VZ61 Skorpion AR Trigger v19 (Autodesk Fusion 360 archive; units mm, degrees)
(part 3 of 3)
sketch "Sketch4" plane through (0, 5.5844, 0) normal (0, -1, 0) x axis (1, 0, 0)
  line L1 (6.8359, 50.875) -> (6.8359, 44)
  line L2 (5.4872, 50.875) -> (6.8359, 50.875)
  line L3 (-6.8359, 50.875) -> (-5.4872, 50.875)
  line L4 (-6.8359, 44) -> (-6.8359, 50.875)
  line L5 (6.8359, 44) -> (-6.8359, 44)
  line L6 (6.8359, 50.5) -> (-6.8359, 50.5)
  line L7 (6.8359, 52) -> (-6.8359, 52)
  line L8 (-6.8359, 50.5) -> (-6.8359, 52)
  line L9 (6.8359, 52) -> (6.8359, 50.5)
  line L10 (-0.5, 51.5) -> (-4.4371, 52)
  line L11 (-0.5, 51) -> (-0.5, 51.5)
  line L12 (-4.4371, 50.5) -> (-0.5, 51)
  line L13 (4.4371, 52) -> (0.5, 51.5)
  line L14 (0.5, 51) -> (0.5, 51.5)
  line L15 (4.4371, 50.5) -> (0.5, 51)
  circle C1 centre (0, 51.25) radius 4.5
  arc A1 centre (0, 51.25) radius 5.5 clockwise from (-5.4872, 50.875) to (5.4872, 50.875)
  circle C2 centre (0, 51.25) radius 4.5
  circle C3 centre (0, 51.25) radius 5.5
  circle C4 centre (0, 51.25) radius 6.8359
  point P11 (-6.8359, 50.5)
  point P12 (6.8359, 50.5)
  point P15 (6.8359, 52)
  point P14 (6.8359, 52)
  point P17 (-4.4371, 52)
  point P20 (-4.4371, 50.5)
  point P22 (4.4371, 52)
  point P24 (4.4371, 50.5)
  point P10 (0, 51.25)
  point P21 (0.5, 51.5)
  point P23 (0.5, 51)
  concentric C1 C2
  concentric C1 C3
  coincident L4 P11
  coincident L1 P12
  perpendicular L1 L6
  horizontal L7
  perpendicular L6 L8
  coincident L7 P15
  perpendicular L7 L9
  coincident P14 P15
  concentric C2 C4
  coincident C2 P17
  coincident L7 P17
  perpendicular L6 L11
  coincident L6 P20
  coincident C2 P20
  coincident C2 P22
  coincident L7 P22
  perpendicular L7 L14
  coincident C2 P24
  coincident L6 P24
  dimension "d16" distance P10 L6 = 0.75 (= "( 1.5 / 2 ) * 1 mm")
  dimension "d17" distance P10 L7 = 0.75
  dimension "d38" distance P21 P23 = 0.5
extrude "Extrude5" cut sketch "Sketch4" profile of C1 L1 L2 A1 L3 L4 C2 C3 L6 L7 L8 L9 against normal blind 2
extrude "Extrude6" cut sketch "Sketch4" profile of L1 L2 C3 L6 L9 against normal blind 2
extrude "Extrude7" cut sketch "Sketch4" profile of C1 A1 C2 C3 L7 against normal blind 2
extrude "Extrude8" cut sketch "Sketch4" profile of C1 C2 C3 L6 against normal blind 2
extrude "Extrude9" cut sketch "Sketch4" profile of C1 A1 C2 C3 L6 L7 against normal blind 2
extrude "Extrude10" cut sketch "Sketch4" profile of C1 A1 C2 C3 L6 L7 against normal blind 2
extrude "Extrude11" new body sketch "Sketch4" profile of C1 A1 C2 C3 L6 L7 against normal blind 2
extrude "Extrude12" new body sketch "Sketch4" profile of L1 L2 A1 L3 L4 C3 L6 L7 L8 L9 against normal blind 2
extrude "Extrude13" new body of existing geometry blind 1.125
extrude "Extrude14" new body sketch "Sketch4" profile of A1 C3 L7 C4 against normal blind 15
combine "Combine1"
combine "Combine2"
combine "Combine3"
delete_face "DeleteFace1"
delete_face "DeleteFace2"
extrude "Extrude15" new body sketch "Sketch4" profile of C1 C2 L8 L10 L11 L12 L13 L14 L15 against normal blind 2 bodies "Rear Sight Ring"
combine "Combine4"
sketch "Sketch5" plane through (10.6045, 0, 0) normal (1, 0, 0) x axis (0, 1, 0)
  line L1 (34.9974, 44) -> (5.5844, 44)
  line L2 (34.9974, 57) -> (34.9974, 44)
  line L3 (5.5844, 57) -> (34.9974, 57)
  line L4 (5.5844, 44) -> (5.5844, 57)
  line L5 (5.5844, 44.4141) -> (5.5844, 58.0859)
  circle C1 centre (14.5844, 46.5) radius 2
  circle C2 centre (14.5844, 46.5) radius 1
  point P7 (14.5844, 46.5)
  point P6 (14.5844, 46.5)
  concentric C1 C2
  dimension "d41" diameter C1 = 4
  dimension "d42" diameter C2 = 2
  dimension "d73" distance L1 P7 = 2.5
  dimension "d74" distance P6 L5 = 9
sketch "Sketch6" plane through (6.8359, 0, 0) normal (1, 0, 0) x axis (0, 1, 0)
  line L1 (20.5844, 52) -> (20.5844, 44)
  line L2 (7.5844, 52) -> (20.5844, 52)
  line L3 (7.5844, 50.5) -> (7.5844, 52)
  line L4 (5.5844, 50.5) -> (7.5844, 50.5)
  line L5 (5.5844, 44) -> (5.5844, 50.5)
  line L6 (20.5844, 44) -> (5.5844, 44)
  line L7 (35, 46.5) -> (35, 44)
  line L8 (20.5844, 46.5) -> (35, 46.5)
  line L9 (35, 46.5) -> (20.5844, 52)
  line L10 (20.5844, 44) -> (35, 44)
  point P10 (20.5844, 46.5)
  point P3 (20.5844, 52)
  point P11 (20.5844, 52)
  point P2 (20.5844, 44)
  point P12 (20.5844, 44)
  perpendicular L2 L7
  coincident L1 P10
  perpendicular L1 L8
  coincident P3 P11
  coincident P2 P12
extrude "Extrude16" new body sketch "Sketch6" profile of L1 L7 L8 L9 L10 against normal blind 13.672 bodies "Rear Sight Fixture"
sketch "Sketch7" plane through (0, 20.5844, 0) normal (0, 1, 0) x axis (-1, 0, 0)
  line L1 (6.8359, 52) -> (6.8359, 44)
  line L2 (6.7946, 52) -> (6.8359, 52)
  line L3 (-6.8359, 52) -> (-6.7946, 52)
  line L4 (-6.8359, 44) -> (-6.8359, 52)
  line L5 (6.8359, 44) -> (-6.8359, 44)
  arc A1 centre (0, 51.25) radius 6.8359 clockwise from (-6.7946, 52) to (6.7946, 52)
  circle C1 centre (0, 51.25) radius 4.5
extrude "Extrude17" cut sketch "Sketch7" profile of C1 along normal blind 25.5
fillet "Fillet1" radius 2.5
sketch "Sketch8" plane through (0, 0, 40.8178) normal (0, 0, -1) x axis (1, 0, 0)
  line L1 (-7.8359, -5.5844) -> (7.8359, -5.5844)
  line L2 (-7.8359, -34.9974) -> (-7.8359, -5.5844)
  line L3 (7.8359, -34.9974) -> (-7.8359, -34.9974)
  line L4 (7.8359, -5.5844) -> (7.8359, -34.9974)
  circle C1 centre (0, -32.2474) radius 1.05
  circle C2 centre (0, -32.2474) radius 2.5
  circle C3 centre (0, -32.2474) radius 2.15
  point P6 (0, -32.2474)
  concentric C1 C2
  concentric C1 C3
  dimension "d48" diameter C1 = 2.1
  dimension "d49" diameter C2 = 5
  dimension "d54" distance L3 P6 = 2.75
  dimension "d55" diameter C3 = 4.3
extrude "Extrude18" cut sketch "Sketch8" profile of L3 C1 C2 against normal blind 1.7
extrude "Extrude19" cut of existing geometry blind -17
extrude "Extrude20" cut sketch "Sketch8" profile of C1 C3 blind 0.1 second side blind 2.5 from offset -6
sketch "Sketch10" plane through (0, 0, 44) normal (0, 0, -1) x axis (1, 0, 0)
  line L1 (-6.8359, -5.5844) -> (6.8359, -5.5844)
  line L2 (-6.8359, -20.5844) -> (-6.8359, -5.5844)
  line L3 (6.8359, -20.5844) -> (-6.8359, -20.5844)
  line L4 (6.8359, -5.5844) -> (6.8359, -20.5844)
  line L5 (12.5, -5.5844) -> (-12.5, -5.5844)
  circle C1 centre (0, -10.0844) radius 1.875
  point P6 (0, -10.0844)
  dimension "d61" diameter C1 = 3.75
  dimension "d62" distance P6 L5 = 4.5
extrude "Extrude21" cut sketch "Sketch10" profile of C1 against normal blind 17.5
sketch "Sketch11" plane through (6.8359, 0, 0) normal (1, 0, 0) x axis (0, 1, 0)
  line L1 (20.5844, 52) -> (35, 46.5)
  line L2 (20.5844, 44) -> (20.5844, 52)
  line L3 (32.5, 44) -> (20.5844, 44)
  line L4 (31.2, 44) -> (31.2, 46.7)
  line L5 (34.9568, 46.0375) -> (33.3, 46.7)
  line L6 (33.3, 46.7) -> (31.2, 46.7)
  line L7 (30.1, 46) -> (32.25, 46.7)
  line L8 (30.1, 46.7) -> (30.1, 46)
  line L9 (32.25, 46.7) -> (30.1, 46.7)
  arc A1 centre (32.5, 46.5) radius 2.5 clockwise from (35, 46.5) to (32.5, 44)
  point P8 (31.2, 44)
  point P10 (34.9568, 46.0375)
  point P11 (32.25, 46.7)
  coincident L3 P8
  perpendicular L3 L4
  coincident A1 P10
  horizontal L6
  midpoint L6 P11
  perpendicular L6 L8
  parallel L6 L9
extrude "Extrude22" cut sketch "Sketch11" profile of A1 L3 L4 L5 L6 L7 L8 L9 blind -2.05 from offset -5.8
extrude "Extrude23" add of existing geometry blind 2.7
delete_face "DeleteFace3"
sketch "Sketch12" plane through (0, 0, 46.7178) normal (0, 0, 1) x axis (-1, 0, 0)
  line L1 (-2.15, -32.2474) -> (0, -32.2474)
  line L2 (2.15, -32.2474) -> (0, -32.2474)
  circle C1 centre (0, -32.2474) radius 1.05
  circle C2 centre (0, -32.2474) radius 2.15
  point P2 (0, -32.2474)
  point P3 (0, -32.2474)
  point P4 (-2.15, -32.2474)
  point P5 (2.15, -32.2474)
  coincident P2 P3
  coincident C2 P4
  horizontal L1
  coincident C2 P5
  parallel L1 L2
revolve "Revolve1" sketch "Sketch12" AlongAngle -10
extrude "Extrude25" cut sketch "Sketch5" profile of C2 against normal blind 26
combine "Combine5"
sketch "Sketch13" plane through (-10.6045, 0, 0) normal (-1, 0, 0) x axis (0, -1, 0)
  line L1 (-5.5844, 44) -> (-34.9974, 44)
  line L2 (-5.5844, 57) -> (-5.5844, 44)
  line L3 (-34.9974, 57) -> (-5.5844, 57)
  line L4 (-34.9974, 44) -> (-34.9974, 57)
  circle C1 centre (-14.5844, 46.5) radius 1
  circle C2 centre (-14.5844, 46.5) radius 2.5
  concentric C1 C2
  dimension "d77" diameter C2 = 5
extrude "Extrude26" cut sketch "Sketch13" profile of C1 C2 against normal blind 2
extrude "Extrude27" cut sketch "Sketch5" profile of C1 C2 against normal blind 2
extrude "Extrude28" cut of existing geometry blind -7
extrude "Extrude29" add of existing geometry blind 3
chamfer "Chamfer1" distance 22 rotateAngle 20
extrude "Extrude31" new body sketch "Base" profile of L1 L7 L8 L9 L11 L12 L13 L14 along normal blind 5 bodies "Front Sight Base"
extrude "Extrude32" new body sketch "Base" profile of L2 L3 L4 L5 L9 L10 L13 L14 along normal blind 5
move "Move1"
combine "Combine6"
extrude "Extrude33" new body of existing geometry blind 3
extrude "Extrude34" new body of existing geometry blind 4.664
combine "Combine7"
combine "Combine8"
sketch "Sketch14" plane through (0, 0.5844, 0) normal (0, -1, 0) x axis (1, 0, 0)
  line L1 (12.5, 31.496) -> (7.8359, 31.496)
  line L2 (12.5, 44) -> (12.5, 31.496)
  line L3 (7.8359, 44) -> (12.5, 44)
  line L4 (7.8359, 40.8178) -> (7.8359, 44)
  line L5 (10.6045, 37.8979) -> (7.8359, 40.8178)
  line L6 (7.8359, 34.9861) -> (10.6045, 37.8979)
  line L7 (7.8359, 31.496) -> (7.8359, 34.9861)
  line L8 (7.8359, 47) -> (7.8359, 44)
  line L9 (10.5, 47) -> (7.8359, 47)
  line L10 (12.5, 47) -> (10.5, 47)
  line L11 (12.5, 44) -> (12.5, 47)
  line L12 (7.8359, 42.8178) -> (5.8359, 42.8178)
  line L13 (7.8359, 40.8178) -> (-7.8359, 40.8178)
  line L14 (5.8359, 44.8178) -> (5.8359, 42.8178)
  line L15 (7.8359, 44.8178) -> (5.8359, 44.8178)
  line L16 (12.5, 44.8178) -> (7.8359, 44.8178)
  point P5 (7.8359, 44)
  point P9 (7.8359, 44)
  point P4 (12.5, 44)
  point P13 (12.5, 44)
  point P15 (7.8359, 42.8178)
  point P19 (7.8359, 44.8178)
  point P20 (12.5, 44.8178)
  point P14 (5.8359, 42.8178)
  point P18 (5.8359, 44.8178)
  coincident P5 P9
  perpendicular L3 L8
  perpendicular L8 L9
  perpendicular L8 L10
  coincident P4 P13
  coincident L4 P15
  perpendicular L4 L12
  perpendicular L12 L14
  coincident L8 P19
  perpendicular L8 L15
  coincident L11 P20
  perpendicular L11 L16
  dimension "d98" distance L12 L13 = 2
  dimension "d99" distance P14 P15 = 2
  dimension "d100" distance P14 P18 = 2
extrude "Extrude35" cut sketch "Sketch14" profile of L3 L8 L9 L10 L11 against normal blind 43
extrude "Extrude36" new body of existing geometry blind 4.664
combine "Combine9"
extrude "Extrude37" cut sketch "Sketch14" profile of L1 L2 L3 L4 L5 L6 L7 L8 L11 L12 L14 L15 L16 against normal blind 59
extrude "Extrude38" new body sketch "Sketch14" profile of L1 L2 L3 L4 L5 L6 L7 L8 L11 L12 L14 L15 L16 against normal blind 34.413 bodies "Rear Sight Clamp"
move "Move2"
sketch "Sketch15" plane through (12.5, 0, 0) normal (1, 0, 0) x axis (0, 1, 0)
  line L1 (0.5844, 31.496) -> (0.5844, 44)
  line L2 (34.9974, 31.496) -> (0.5844, 31.496)
  line L3 (34.9974, 44) -> (34.9974, 31.496)
  line L4 (0.5844, 44) -> (34.9974, 44)
  line L5 (34.9974, 37.8979) -> (0.5844, 37.8979)
  line L6 (19.23, 39.9979) -> (13.9976, 39.9979)
  line L7 (19.23, 37.8979) -> (19.23, 40.8178)
  line L8 (13.9976, 40.8178) -> (13.9976, 37.8979)
  circle C1 centre (16.6138, 39.9979) radius 2.1
  circle C2 centre (16.6138, 39.9979) radius 3.5
  point P10 (19.23, 39.9979)
  point P9 (13.9976, 39.9979)
  point P6 (16.6138, 39.9979)
  tangent C1 L5
  horizontal L6
  coincident P10 L7
  coincident P9 L8
  midpoint P6 L6
  concentric C1 C2
  dimension "d109" diameter C1 = 4.2
  dimension "d110" diameter C2 = 7
extrude "Extrude39" cut sketch "Sketch15" profile of C1 L6 against normal blind 75
extrude "Extrude40" cut sketch "Sketch15" profile of C1 L5 L6 L7 L8 C2 against normal blind 1
sketch "Sketch16" plane through (-12.5, 0, 0) normal (-1, 0, 0) x axis (0, -1, 0)
  line L1 (-0.5844, 31.496) -> (-34.9974, 31.496)
  line L2 (-0.5844, 47) -> (-0.5844, 31.496)
  line L3 (-34.9974, 47) -> (-0.5844, 47)
  line L4 (-34.9974, 31.496) -> (-34.9974, 47)
  circle C1 centre (-16.6138, 39.9979) radius 2.1
  circle C2 centre (-16.6138, 39.9979) radius 4
  concentric C1 C2
  dimension "d115" diameter C2 = 8
extrude "Extrude41" cut sketch "Sketch16" profile of C1 C2 against normal blind 1.75
fillet "Fillet2" radius 2
fillet "Fillet3" radius 2
fillet "Fillet4" radius 2
combine "Combine10"
sketch "Sketch17" plane through (0, 150.04, 0) normal (0, 1, 0) x axis (-1, 0, 0)
  line L1 (-10.6045, 37.8979) -> (-7.8359, 40.8178)
  line L2 (-7.8359, 34.9861) -> (-10.6045, 37.8979)
  line L3 (-7.8359, 31.496) -> (-7.8359, 34.9861)
  line L4 (7.8359, 31.496) -> (-7.8359, 31.496)
  line L5 (7.8359, 35.0314) -> (7.8359, 31.496)
  line L6 (10.6045, 37.9286) -> (7.8359, 35.0314)
  line L7 (7.8359, 40.8178) -> (10.6045, 37.9286)
  line L8 (-7.8359, 40.8178) -> (7.8359, 40.8178)
  line L9 (0.5, 47) -> (0.5, 54.3)
  line L10 (-0.4943, 47) -> (-0.5, 54.2996)
  line L11 (0.5, 47) -> (-0.4943, 47)
  line L12 (-10.4999, 47) -> (10.5, 47)
  line L13 (0.0028, 47) -> (0, 54.3)
  line L14 (-0.0002, 54.8) -> (0, 54.3)
  circle C1 centre (0, 54.3) radius 0.5
  point P11 (0.5, 54.3)
  point P13 (-0.5, 54.2996)
  point P10 (0, 54.3)
  point P17 (0, 54.3)
  point P18 (0.0028, 47)
  point P19 (0, 54.3)
  point P20 (-0.0002, 54.8)
  coincident C1 P11
  tangent C1 L9
  vertical L9
  coincident C1 P13
  tangent C1 L10
  collinear L11 L12
  coincident P10 P17
  midpoint L11 P18
  coincident P10 P19
  coincident C1 P20
  parallel L13 L14
revolve "Revolve2" sketch "Sketch17" AlongAngle 360
copy_paste_bodies "CopyPasteBodies1"
move "Move3"
move_face "MoveFace1"
extrude "Extrude42" cut of existing geometry blind -7
delete_face "DeleteFace4"
sketch "Sketch18" plane through (0, 149.9974, 0) normal (0, 1, 0) x axis (-1, 0, 0)
  line L1 (7.8359, 53.5922) -> (10.6045, 53.5922)
  line L2 (7.8359, 47) -> (7.8359, 53.5922)
  line L3 (-7.8359, 47) -> (7.8359, 47)
  line L4 (-7.8359, 53.5922) -> (-7.8359, 47)
  line L5 (-10.6045, 53.5922) -> (-7.8359, 53.5922)
  line L6 (-10.6045, 47) -> (-10.6045, 53.5922)
  line L7 (-10.4999, 47) -> (-10.6045, 47)
  line L8 (-12.4999, 44.8178) -> (-12.4999, 45)
  line L9 (-7.8359, 44.8178) -> (-12.4999, 44.8178)
  line L10 (-5.8359, 44.8178) -> (-7.8359, 44.8178)
  line L11 (-5.8359, 42.8178) -> (-5.8359, 44.8178)
  line L12 (-7.8359, 42.8178) -> (-5.8359, 42.8178)
  line L13 (-7.8359, 40.8178) -> (-7.8359, 42.8178)
  line L14 (7.8359, 40.8178) -> (-7.8359, 40.8178)
  line L15 (10.6045, 37.9286) -> (7.8359, 40.8178)
  line L16 (7.8359, 35.0314) -> (10.6045, 37.9286)
  line L17 (7.8359, 31.496) -> (7.8359, 35.0314)
  line L18 (12.5, 31.496) -> (7.8359, 31.496)
  line L19 (12.5, 45) -> (12.5, 31.496)
  line L20 (10.6045, 47) -> (10.5, 47)
  line L21 (10.6045, 53.5922) -> (10.6045, 47)
  line L22 (0.5, 54.3) -> (-0.5, 54.3)
  line L23 (7.8359, 47) -> (0.5, 54.3)
  line L24 (-7.8359, 47) -> (-0.5, 54.3)
  arc A1 centre (-10.4999, 45) radius 2 clockwise from (-12.4999, 45) to (-10.4999, 47)
  arc A2 centre (10.5, 45) radius 2 clockwise from (10.5, 47) to (12.5, 45)
  point P4 (7.8359, 47)
  point P29 (7.8359, 47)
  point P5 (-7.8359, 47)
  point P30 (-7.8359, 47)
  horizontal L22
  coincident P4 P29
  coincident P5 P30
extrude "Extrude43" add sketch "Sketch18" profile of L3 L22 L23 L24 against normal blind 29.413
delete_face "DeleteFace5"
extrude "Extrude44" cut of existing geometry blind -39
extrude "Extrude45" cut of existing geometry blind -34
extrude "Extrude46" cut of existing geometry blind -23
extrude "Extrude47" cut of existing geometry blind -27
chamfer "Chamfer2" distance 7 rotateAngle 75
sketch "Sketch19" plane through (0, -3.7474, 13.9854) normal (0, -0.2588, 0.9659) x axis (1, 0, 0)
  line L1 (-7.5344, 128.7177) -> (-0.5, 155.7636)
  line L2 (7.5344, 128.7177) -> (-7.5344, 128.7177)
  line L3 (0.5, 155.7636) -> (7.5344, 128.7177)
  line L4 (-0.5, 155.7636) -> (0.5, 155.7636)
  line L5 (0, 128.7177) -> (0, 155.7636)
  line L6 (-5, 128.7177) -> (0, 128.7177)
  line L7 (-0.5, 155.7636) -> (-5, 128.7177)
  line L8 (5, 128.7177) -> (0, 128.7177)
  line L9 (0.5, 155.7636) -> (5, 128.7177)
  point P6 (0, 155.7636)
  point P7 (0, 128.7177)
  point P8 (-5, 128.7177)
  point P2 (-0.5, 155.7636)
  point P9 (-0.5, 155.7636)
  point P10 (5, 128.7177)
  point P5 (0.5, 155.7636)
  point P11 (0.5, 155.7636)
  midpoint L4 P6
  midpoint L2 P7
  coincident L2 P8
  coincident P2 P9
  coincident L2 P10
  coincident P5 P11
  dimension "d136" distance P7 P8 = 5
  dimension "d137" distance P7 P10 = 5
sketch "Sketch20" plane through (0, 149.9974, 0) normal (0, 1, 0) x axis (-1, 0, 0)
  line L1 (-10.4999, 47) -> (-7.8359, 47)
  line L2 (-12.4999, 44.8178) -> (-12.4999, 45)
  line L3 (-7.8359, 44.8178) -> (-12.4999, 44.8178)
  line L4 (-5.8359, 44.8178) -> (-7.8359, 44.8178)
  line L5 (-5.8359, 42.8178) -> (-5.8359, 44.8178)
  line L6 (-7.8359, 42.8178) -> (-5.8359, 42.8178)
  line L7 (-7.8359, 40.8178) -> (-7.8359, 42.8178)
  line L8 (7.8359, 40.8178) -> (-7.8359, 40.8178)
  line L9 (10.6045, 37.9286) -> (7.8359, 40.8178)
  line L10 (7.8359, 35.0314) -> (10.6045, 37.9286)
  line L11 (7.8359, 31.496) -> (7.8359, 35.0314)
  line L12 (12.5, 31.496) -> (7.8359, 31.496)
  line L13 (12.5, 45) -> (12.5, 31.496)
  line L14 (7.8359, 47) -> (10.5, 47)
  line L15 (0.5, 54.3) -> (7.8359, 47)
  line L16 (-0.5, 54.3) -> (0.5, 54.3)
  line L17 (-7.8359, 47) -> (-0.5, 54.3)
  arc A1 centre (-10.4999, 45) radius 2 clockwise from (-12.4999, 45) to (-10.4999, 47)
  arc A2 centre (10.5, 45) radius 2 clockwise from (10.5, 47) to (12.5, 45)
  circle C1 centre (0, 54.3) radius 0.5
  point P23 (0, 54.3)
  point P21 (0.5, 54.3)
  midpoint L16 P23
  coincident P21 C1
extrude "Extrude48" cut sketch "Sketch20" profile of L16 C1 against normal blind 19
extrude "Extrude49" cut sketch "Sketch19" profile of L2 L4 L5 L6 L7 L8 L9 against normal blind 2
extrude "Extrude50" new body of existing geometry blind 2 bodies "Front Sight Ramp"
extrude "Extrude51" cut sketch "Sketch20" profile of L16 C1 against normal blind 13.8
fillet "Fillet5" radius 1
extrude "Extrude52" cut of existing geometry blind -2
delete_face "DeleteFace6"
sketch "Sketch21" plane through (6.8359, 0, 0) normal (1, 0, 0) x axis (0, 1, 0)
  line L1 (20.5844, 55) -> (41.5525, 47)
  line L2 (7.5844, 55) -> (20.5844, 55)
  line L3 (7.5844, 53.5) -> (7.5844, 55)
  line L4 (5.5844, 53.5) -> (7.5844, 53.5)
  line L5 (5.5844, 47) -> (5.5844, 53.5)
  line L6 (20.5844, 47) -> (5.5844, 47)
  line L7 (41.5525, 47) -> (20.5844, 47)
  line L8 (34.9974, 47) -> (34.9974, 49.501)
  line L9 (34.9974, 53.5922) -> (34.9974, 47)
  line L10 (41.5525, 47) -> (34.9974, 49.501)
  line L11 (41.5525, 47) -> (34.9974, 47)
  circle C1 centre (14.5844, 49.5) radius 1
  point P10 (34.9974, 49.501)
  point P11 (34.9974, 47)
  point P3 (41.5525, 47)
  point P14 (41.5525, 47)
  point P12 (34.9974, 47)
  point P15 (34.9974, 47)
  coincident L1 P10
  coincident L7 P11
  perpendicular L7 L8
  collinear L8 L9
  coincident P3 P14
  coincident P12 P15
extrude "Extrude53" cut sketch "Sketch21" profile of L1 L7 L8 L9 L10 L11 against normal blind 31.5
chamfer "Chamfer3" distance 13 rotateAngle 20
fillet "Fillet6" radius 2.5
offset_faces "OffsetFaces1" distance -0.15
sketch "Sketch22" plane through (10.6045, 0, 0) normal (1, 0, 0) x axis (0, 1, 0)
  line L1 (12.9974, 63) -> (33.6814, 55.4716)
  line L2 (7.5844, 63) -> (12.9974, 63)
  line L3 (5.5844, 47) -> (5.5844, 61)
  line L4 (34.9974, 47) -> (5.5844, 47)
  line L5 (34.9974, 53.5922) -> (34.9974, 47)
  arc A1 centre (32.9974, 53.5922) radius 2 clockwise from (33.6814, 55.4716) to (34.9974, 53.5922)
  arc A2 centre (7.5844, 61) radius 2 clockwise from (5.5844, 61) to (7.5844, 63)
  circle C1 centre (14.5844, 49.5) radius 2
  circle C2 centre (32.5, 49) radius 17.9226
  circle C3 centre (14.9868, 52.8088) radius 1
  circle C4 centre (14.9868, 52.8088) radius 2
  circle C5 centre (14.5844, 49.5) radius 2
  circle C6 centre (14.5844, 49.5) radius 1
  circle C7 centre (32.5, 49) radius 19.9217
  circle C8 centre (32.5, 49) radius 15.9226
  circle C9 centre (32.5, 49) radius 18.9226
  circle C10 centre (32.5, 49) radius 16.9226
  point P11 (14.5844, 49.5)
  point P13 (14.9868, 52.8088)
  coincident P11 C2
  coincident C2 P13
  concentric C3 C4
  concentric C1 C5
  concentric C1 C6
  concentric C2 C7
  concentric C2 C8
  tangent C4 C8
  concentric C8 C9
  concentric C9 C10
  tangent C3 C10
  tangent C6 C9
  tangent C3 C9
  dimension "d155" diameter C3 = 2
  dimension "d156" diameter C4 = 4
extrude "Extrude54" cut sketch "Sketch22" profile of C1 C2 C3 C4 C5 C7 C8 against normal blind 2
extrude "Extrude55" cut sketch "Sketch22" profile of C1 C2 C3 C4 C5 C6 C9 C10 against normal blind 56
sketch "Sketch23" plane through (-10.6045, 0, 0) normal (-1, 0, 0) x axis (0, -1, 0)
  line L1 (-5.5844, 47) -> (-14.5844, 47)
  line L2 (-5.5844, 61) -> (-5.5844, 47)
  line L3 (-12.9974, 63) -> (-7.5844, 63)
  line L4 (-33.6814, 55.4716) -> (-12.9974, 63)
  line L5 (-34.9974, 47) -> (-34.9974, 53.5922)
  line L6 (-14.5844, 47) -> (-34.9974, 47)
  arc A1 centre (-32.5, 49) radius 18.9226 clockwise from (-14.0096, 53.0213) to (-13.7967, 51.8727)
  arc A2 centre (-14.5844, 49.5) radius 2.5 clockwise from (-13.7967, 51.8727) to (-14.5844, 47)
  arc A3 centre (-7.5844, 61) radius 2 clockwise from (-7.5844, 63) to (-5.5844, 61)
  arc A4 centre (-32.9974, 53.5922) radius 2 clockwise from (-34.9974, 53.5922) to (-33.6814, 55.4716)
  arc A5 centre (-14.5844, 49.5) radius 2.5 clockwise from (-14.5844, 47) to (-15.7924, 51.6888)
  arc A6 centre (-32.5, 49) radius 16.9226 clockwise from (-15.964, 52.5963) to (-15.7924, 51.6888)
  arc A7 centre (-14.9868, 52.8088) radius 1 clockwise from (-15.964, 52.5963) to (-14.0096, 53.0213)
  circle C1 centre (-32.5, 49) radius 17.9226
  circle C2 centre (-14.5844, 49.5) radius 2.5
  circle C3 centre (-32.5, 49) radius 15.4226
  circle C4 centre (-32.5, 49) radius 20.4226
  circle C5 centre (-14.9868, 52.8088) radius 2.5
  point P6 (-14.5844, 49.5)
  concentric A1 C1
  coincident P6 C1
  concentric A2 C2
  concentric C1 C3
  tangent A5 C3
  tangent C2 C3
  concentric A1 C4
  tangent A2 C4
  concentric A7 C5
  tangent C4 C5
extrude "Extrude56" cut sketch "Sketch23" profile of A1 A2 A5 A6 A7 C1 C2 C3 C4 C5 against normal blind 2
chamfer "Chamfer4" distance 1 rotateAngle 45
fillet "Fillet7" radius 1
fillet "Fillet8" sketch "Sketch15" radius 0.5
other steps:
derived_base_feature "Derived Base Feature" bodies "Picatinny Base"
base_feature "Base Feature" bodies "Front Sight Clamp"
named bodies: "Picatinny Base", "Rear Sight Base", "Rear Sight Ring", "Rear Sight Fixture", "Front Sight Base", "Rear Sight Clamp", "Front Sight Clamp", "Front Sight Ramp"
